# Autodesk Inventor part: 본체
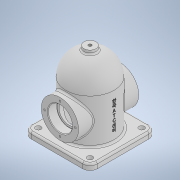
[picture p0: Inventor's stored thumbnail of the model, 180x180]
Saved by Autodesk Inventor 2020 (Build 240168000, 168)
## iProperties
Created: 2021-07
Part Number: 본체
Material: 일반
Document SubType Name: Modeling
Designer: Owner
Density: 1 g/cm^3
Appearance: 기본값
Author: Owner
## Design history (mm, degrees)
sketch "스케치2"
  geometry: C1 r 40 at (0, 0); 1 further point
  constraints: 1 centre point, 1 coincident
  dimensions: "d0" = 80 diameter of C1
extrude "돌출1" new body sketch "스케치2" distance "d1" = 124; taper "d2" = 0 deg
fillet "모깎기1" dims "d3" = 40
feature "쉘1" dims "d4" = 8
node "작업 평면1"
sketch "스케치3"
  geometry: C1 r 31 at (0, 48); 1 further point
  constraints: 1 centre point, 1 vertical alignment
  dimensions: "d6" = 62 diameter of C1; "d7" = 48 distance of point (0, 0) C1.centre
extrude "돌출2" join sketch "스케치3" stored distance "d8" = 124; taper "d9" = 0 deg
sketch "스케치4"
  geometry: C1 r 31 at (0, 0) reference; 2 further points
  constraints: 1 coincident
hole "구멍1" sketch "스케치4" at (0, 0) diameter "d10" = 33; stored, may be unused: countersink angle "d14" = 90 deg, drill point angle "d16" = 0 deg; dims "d11" = 6, "d12" = 40, "d13" = 15, "d15" = 8
sketch "스케치5"
  geometry: C1 r 16.5 at (0, 48) reference; 2 further points
  constraints: 1 vertical alignment
  dimensions: "d17" = 25.5 distance of C1.centre point (0, 73.5)
hole "구멍2" sketch "스케치5" at (0, 73.5) diameter "d18" = 3.242; stored, may be unused: countersink angle "d22" = 90 deg, drill point angle "d24" = 118 deg; dims "d19" = 8, "d20" = 40, "d21" = 15, "d23" = 10
fillet "모깎기2" dims "d28" = 0.3
node "작업 평면2"
sketch "스케치6"
  geometry: C1 r 10 at (0, 0); 1 further point
  constraints: 1 centre point, 1 coincident
  dimensions: "d30" = 20 diameter of C1
extrude "돌출3" join sketch "스케치6" stored distance "d31" = 124; taper "d32" = 0 deg
sketch "스케치7"
  geometry: C1 r 10 at (0, 0) reference; 2 further points
  constraints: 1 coincident
hole "구멍3" sketch "스케치7" at (0, 0) diameter "d33" = 5.1881; stored, may be unused: countersink angle "d37" = 90 deg, drill point angle "d39" = 118 deg; dims "d34" = 30, "d35" = 40, "d36" = 15, "d38" = 16
sketch "스케치8"
  geometry: L1 (-55, -55)-(55, -55); L2 (55, -55)-(55, 55); L3 (55, 55)-(-55, 55); L4 (-55, 55)-(-55, -55); L5 (-55, -55)-(55, 55); L6 (55, -55)-(-55, 55); C1 r 2.594 at (0, 0) reference; C2 r 40 at (0, 0) reference; 1 further point
  constraints: 12 end point, 2 midpoint, 2 parallel, 1 horizontal, 1 perpendicular
  dimensions: "d40" = 110 distance of L3.end L2.end; "d41" = 110 distance of L2.end L1.end
extrude "돌출4" join sketch "스케치8" distance "d42" = 10; taper "d43" = 0 deg
fillet "모깎기3" dims "d44" = 12
fillet "모깎기4" dims "d45" = 3
sketch "스케치9"
  geometry: A1 r 9 centre (43, -43) between (43, -52) and (52, -43) reference; 2 further points
  constraints: 1 coincident
hole "구멍4" sketch "스케치9" at (43, -43) diameter "d46" = 9; stored, may be unused: countersink angle "d50" = 90 deg, drill point angle "d52" = 118 deg; dims "d47" = 30, "d48" = 40, "d49" = 15, "d51" = 16
node "작업 평면3"
sketch "스케치10"
  geometry: L1 (0, -43)-(0, 43) reference; L2 (71.992, 3.474)-(71.992, -3.474); L3 (71.992, -3.474)-(24.008, -3.474); L4 (24.008, -3.474)-(24.008, 3.474); L5 (24.008, 3.474)-(71.992, 3.474); 2 further points
  constraints: 1 midpoint, 2 other
feature "엠보싱1" sketch "스케치10" dims "d55" = 0.5, "d56" = 0
chamfer "모따기1" distance "d57" = 1; stored, may be unused: second distance "d58" = 2, angle "d59" = 45 deg
node "솔리드1"
pattern_circular "원형 패턴1" dims angle "d26" = 360 deg
mirror "미러1"
mirror "미러2"
mirror "미러3"
feature "A9D066F2-1C7D-4E18-AEED-F7BC21143FA4" dims "d10" = 33, "d11" = 6, "d12" = 40, "d13" = 15, "d14" = 90 deg, "d15" = 8, "d16" = 0
other parameters: "d29" = 129
